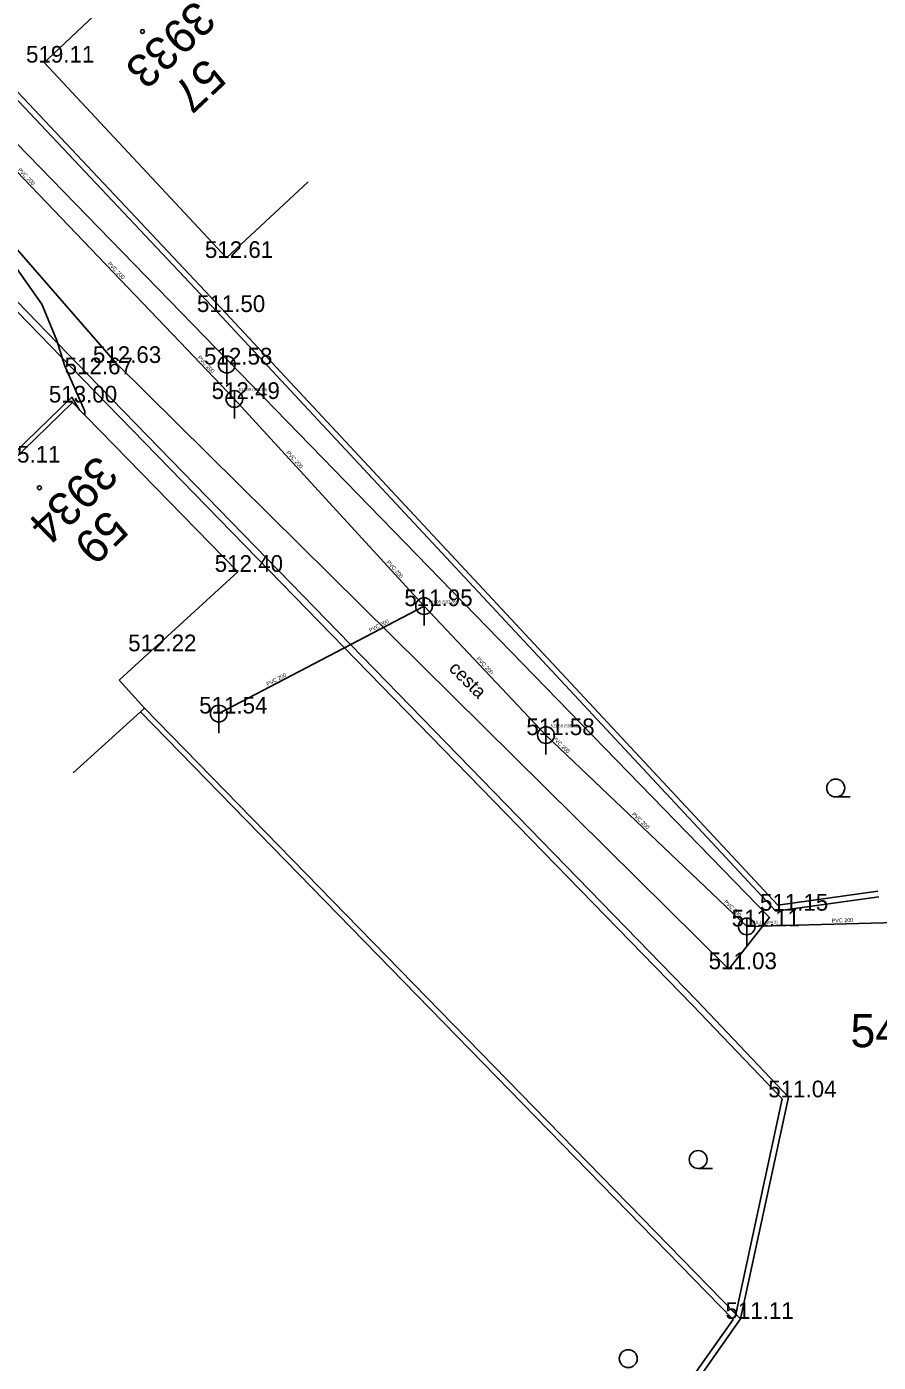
# Model space of a CAD drawing. Extents: x -668867 to -667827, y -1131943 to -1131019.
# Drawn here: x -668359.3 to -668321.1, y -1131321.7 to -1131261.7 of the extents above; entities that cross this region are included whole.
import ezdxf

# ---------------------------------------------------------------- set-up
doc = ezdxf.new("R2010")
doc.units = 0
for name, color, linetype in [('G_Bod_tecka', 7, 'Continuous'), ('G_Bod_vyska', 7, 'Continuous'), ('G_Bodove_pole', 7, 'Continuous'), ('G_Budovy-znacky', 7, 'Continuous'), ('G_Budovy_Objekty', 7, 'Continuous'), ('G_Budovy_vstupy', 7, 'Continuous'), ('G_Cesty_Schody', 7, 'Continuous'), ('G_Cisla_orientacni', 7, 'Continuous'), ('G_Cisla_popisna', 7, 'Continuous'), ('G_Ploty', 7, 'Continuous'), ('G_Popisy_povrchu', 7, 'Continuous'), ('G_Site-kanalizace', 7, 'Continuous'), ('G_Z_ELsilove_podz_kotovane', 7, 'Continuous'), ('G_Z_KANAL_podz_kotovane', 7, 'Continuous'), ('G_Zelen-Znacky', 7, 'Continuous'), ('Vrstva 13', 7, 'Continuous'), ('Vrstva 2', 7, 'Continuous'), ('Vrstva 3', 7, 'Continuous'), ('Vrstva 8', 7, 'Continuous')]:
    doc.layers.add(name, color=color, linetype=linetype)

msp = doc.modelspace()

# ---------------------------------------------------------------- linework, layer by layer
at = {"layer": 'G_Bod_tecka'}
for p, q in [((-668358.55, -1131263.28), (-668358.55, -1131263.28)), ((-668350.36, -1131272.06), (-668350.36, -1131272.06)), ((-668350.79, -1131274.49), (-668350.79, -1131274.49)), ((-668356.61, -1131277.29), (-668356.61, -1131277.29)), ((-668355.34, -1131276.78), (-668355.34, -1131276.78)), ((-668350.35, -1131276.85), (-668350.35, -1131276.85)), ((-668357.28, -1131278.56), (-668357.28, -1131278.56)), ((-668350.01, -1131278.4), (-668350.01, -1131278.4)), ((-668349.85, -1131286.17), (-668349.85, -1131286.17)), ((-668341.49, -1131287.71), (-668341.49, -1131287.71)), ((-668353.76, -1131289.74), (-668353.76, -1131289.74)), ((-668350.71, -1131292.54), (-668350.71, -1131292.54)), ((-668336.01, -1131293.51), (-668336.01, -1131293.51)), ((-668325.66, -1131301.4), (-668325.66, -1131301.4)), ((-668326.99, -1131302.11), (-668326.99, -1131302.11)), ((-668327.8, -1131304.03), (-668327.8, -1131304.03)), ((-668325.12, -1131309.79), (-668325.12, -1131309.79)), ((-668327.27, -1131319.75), (-668327.27, -1131319.75))]:
    msp.add_line(p, q, dxfattribs=at)
at = {"layer": 'G_Budovy-znacky'}
for centre in [(-668354.14, -1131261.88), (-668358.77, -1131282.39)]:
    msp.add_circle(centre, 0.0875, dxfattribs=at)
at = {"layer": 'G_Budovy_Objekty'}
for p, q in [((-668358.15, -1131262.9), (-668358.55, -1131263.28)), ((-668358.55, -1131263.28), (-668350.36, -1131272.06)), ((-668346.7, -1131268.64), (-668350.36, -1131272.06)), ((-668360.06, -1131281.26), (-668357.28, -1131278.56)), ((-668349.85, -1131286.17), (-668357.28, -1131278.56)), ((-668349.85, -1131286.17), (-668353.02, -1131289.06)), ((-668355.19, -1131291.04), (-668353.76, -1131289.74)), ((-668355.19, -1131291.04), (-668354.05, -1131292.3)), ((-668354.23, -1131292.46), (-668354.05, -1131292.3)), ((-668357.25, -1131295.21), (-668354.23, -1131292.46))]:
    msp.add_line(p, q, dxfattribs=at)
at = {"layer": 'G_Budovy_vstupy'}
for p, q in [((-668356.3, -1131261.14), (-668358.15, -1131262.9)), ((-668353.76, -1131289.74), (-668353.02, -1131289.06))]:
    msp.add_line(p, q, dxfattribs=at)
at = {"layer": 'G_Cesty_Schody'}
for points in [[(-668325.96, -1131301.71), (-668362.46, -1131264.17)], [(-668355.34, -1131276.78), (-668364.33, -1131266.46)], [(-668327.8, -1131304.03), (-668355.34, -1131276.78)], [(-668327.8, -1131304.03), (-668325.96, -1131301.71)]]:
    msp.add_lwpolyline(points, dxfattribs=at)
at = {"layer": 'G_Ploty'}
for p, q in [((-668364.94, -1131259.46), (-668350.79, -1131274.49)), ((-668350.6, -1131274.32), (-668364.61, -1131259.45)), ((-668366.58, -1131267.46), (-668356.83, -1131277.49)), ((-668366.37, -1131267.25), (-668356.61, -1131277.29)), ((-668325.59, -1131301.15), (-668350.6, -1131274.32)), ((-668350.79, -1131274.49), (-668325.68, -1131301.42)), ((-668356.61, -1131277.29), (-668329.21, -1131305.46)), ((-668356.83, -1131277.49), (-668329.43, -1131305.65)), ((-668354.05, -1131292.3), (-668327.48, -1131319.54)), ((-668354.23, -1131292.46), (-668327.6, -1131319.78)), ((-668325.68, -1131301.42), (-668321.06, -1131300.78)), ((-668321.1, -1131300.53), (-668325.59, -1131301.15)), ((-668329.21, -1131305.46), (-668325.12, -1131309.79)), ((-668329.43, -1131305.65), (-668325.4, -1131309.86)), ((-668327.27, -1131319.75), (-668325.12, -1131309.79)), ((-668325.4, -1131309.86), (-668327.48, -1131319.54)), ((-668327.6, -1131319.78), (-668329.97, -1131323.13)), ((-668329.76, -1131323.28), (-668327.27, -1131319.75)), ((-668327.48, -1131319.54), (-668327.27, -1131319.75))]:
    msp.add_line(p, q, dxfattribs=at)
at = {"layer": 'G_Site-kanalizace'}
for p, q in [((-668350.35, -1131276.475), (-668350.35, -1131277.725)), ((-668350.01, -1131278.025), (-668350.01, -1131279.275)), ((-668341.49, -1131287.335), (-668341.49, -1131288.585)), ((-668350.71, -1131292.165), (-668350.71, -1131293.415)), ((-668336.01, -1131293.135), (-668336.01, -1131294.385)), ((-668326.99, -1131301.735), (-668326.99, -1131302.985))]:
    msp.add_line(p, q, dxfattribs=at)
for centre in [(-668350.35, -1131276.85), (-668350.01, -1131278.4), (-668341.49, -1131287.71), (-668350.71, -1131292.54), (-668336.01, -1131293.51), (-668326.99, -1131302.11)]:
    msp.add_circle(centre, 0.375, dxfattribs=at)
at = {"layer": 'G_Z_ELsilove_podz_kotovane'}
for points in [[(-668366.816, -1131267.066), (-668365.864, -1131266.277), (-668365.079, -1131266.301), (-668362.287, -1131269.021), (-668358.668, -1131274.134), (-668357.991, -1131275.777), (-668357.648, -1131276.873), (-668356.723, -1131278.942), (-668356.732, -1131279.124)], [(-668356.958, -1131278.915), (-668357.31, -1131278.32), (-668362.973, -1131283.803), (-668362.029, -1131285.001), (-668364.143, -1131287.083), (-668367.041, -1131289.937), (-668366.076, -1131290.956), (-668368.256, -1131293.067), (-668371.205, -1131295.923), (-668370.187, -1131297.06), (-668372.244, -1131299.042), (-668375.182, -1131301.874), (-668374.215, -1131302.98), (-668376.367, -1131305.053), (-668379.275, -1131307.854), (-668378.308, -1131308.983), (-668380.474, -1131311.08), (-668383.435, -1131313.945), (-668382.468, -1131315.051), (-668384.4, -1131316.964), (-668387.483, -1131320.017), (-668386.494, -1131321.123), (-668389.081, -1131323.512)]]:
    msp.add_lwpolyline(points, dxfattribs=at)
at = {"layer": 'G_Z_KANAL_podz_kotovane'}
for p, q in [((-668350.02, -1131278.39), (-668341.49, -1131287.71)), ((-668350.71, -1131292.54), (-668341.49, -1131287.71)), ((-668341.49, -1131287.71), (-668336.01, -1131293.51)), ((-668336.01, -1131293.51), (-668326.99, -1131302.11)), ((-668326.99, -1131302.11), (-668309.39, -1131301.63))]:
    msp.add_line(p, q, dxfattribs=at)
msp.add_lwpolyline([(-668370.12, -1131257.37), (-668352.13, -1131276.17), (-668350.02, -1131278.39)], dxfattribs=at)
at = {"layer": 'G_Zelen-Znacky'}
for p, q in [((-668322.992, -1131296.29), (-668322.342, -1131296.287)), ((-668329.172, -1131312.99), (-668328.522, -1131312.987))]:
    msp.add_line(p, q, dxfattribs=at)
for centre in [(-668322.993, -1131295.887), (-668329.173, -1131312.587), (-668332.313, -1131321.537)]:
    msp.add_circle(centre, 0.403, dxfattribs=at)
at = {"layer": 'Vrstva 13'}
for p, q in [((-668350.02, -1131278.39), (-668341.49, -1131287.71)), ((-668350.71, -1131292.54), (-668341.49, -1131287.71)), ((-668341.49, -1131287.71), (-668336.01, -1131293.51)), ((-668336.01, -1131293.51), (-668326.99, -1131302.11)), ((-668326.99, -1131302.11), (-668309.39, -1131301.63))]:
    msp.add_line(p, q, dxfattribs=at)
msp.add_lwpolyline([(-668370.12, -1131257.37), (-668352.13, -1131276.17), (-668350.02, -1131278.39)], dxfattribs=at)
at = {"layer": 'Vrstva 8'}
for p, q in [((-668350.02, -1131278.39), (-668350.02, -1131278.39)), ((-668341.49, -1131287.71), (-668341.49, -1131287.71)), ((-668336.01, -1131293.51), (-668336.01, -1131293.51)), ((-668326.99, -1131302.11), (-668326.99, -1131302.11))]:
    msp.add_line(p, q, dxfattribs=at)

# ---------------------------------------------------------------- texts
at = {"layer": 'G_Bod_vyska'}
for s, p in [('519.11', (-668359.371, -1131263.28)), ('512.61', (-668351.334, -1131272.06)), ('511.50', (-668351.692, -1131274.49)), ('512.63', (-668356.366, -1131276.78)), ('512.58', (-668351.372, -1131276.85)), ('512.67', (-668357.636, -1131277.29)), ('513.00', (-668358.346, -1131278.56)), ('512.49', (-668351.034, -1131278.4)), ('515.11', (-668360.889, -1131281.26)), ('512.40', (-668350.894, -1131286.17)), ('511.95', (-668342.373, -1131287.71)), ('512.22', (-668354.782, -1131289.74)), ('511.54', (-668351.591, -1131292.54)), ('511.58', (-668336.891, -1131293.51)), ('511.15', (-668326.396, -1131301.4)), ('511.11', (-668327.667, -1131302.11)), ('511.03', (-668328.702, -1131304.03)), ('511.04', (-668326.022, -1131309.79)), ('511.11', (-668327.947, -1131319.75))]:
    msp.add_text(s, height=0.75, dxfattribs=at).set_placement(p)
at = {"layer": 'G_Bodove_pole'}
msp.add_text('5431', height=1.5, dxfattribs=at).set_placement((-668322.328, -1131307.54))
at = {"layer": 'G_Cisla_orientacni'}
for s, rotation, p in [('57', 223.08054, (-668351.297, -1131263.01)), ('59', 224.06938, (-668355.708, -1131283.309))]:
    msp.add_text(s, height=1.5, rotation=rotation, dxfattribs=at).set_placement(p)
at = {"layer": 'G_Cisla_popisna'}
for s, rotation, p in [('3933', 223.08054, (-668351.749, -1131260.407)), ('3934', 224.06938, (-668356.151, -1131280.853))]:
    msp.add_text(s, height=1.5, rotation=rotation, dxfattribs=at).set_placement(p)
at = {"layer": 'G_Popisy_povrchu'}
msp.add_text('cesta', height=0.6, rotation=315.29279, dxfattribs=at).set_placement((-668340.413, -1131290.558))
at = {"layer": 'Vrstva 2'}
for s, p in [('512.49 (509.89)', (-668349.814, -1131278.037)), ('511.95 (507.85)', (-668341.285, -1131287.588)), ('511.58 (505.62)', (-668335.804, -1131293.157)), ('511.11 (504.2)', (-668326.785, -1131301.988))]:
    msp.add_text(s, height=0.13163, dxfattribs=at).set_placement(p)
at = {"layer": 'Vrstva 3'}
for rotation, p in [(313.73765, (-668359.75, -1131268.112)), (313.74941, (-668355.713, -1131272.334)), (313.71308, (-668351.677, -1131276.555)), (312.48642, (-668347.693, -1131280.828)), (312.43838, (-668343.187, -1131285.752)), (27.59935, (-668343.905, -1131288.895)), (313.37647, (-668339.147, -1131290.087)), (27.67538, (-668348.515, -1131291.311)), (315.99792, (-668335.738, -1131293.667)), (316.34676, (-668332.162, -1131297.082)), (316.38252, (-668328.031, -1131301.021)), (1.56377, (-668323.172, -1131301.935))]:
    msp.add_text('PVC 200', height=0.1755, rotation=rotation, dxfattribs=at).set_placement(p)

doc.saveas('drawing.dxf')
